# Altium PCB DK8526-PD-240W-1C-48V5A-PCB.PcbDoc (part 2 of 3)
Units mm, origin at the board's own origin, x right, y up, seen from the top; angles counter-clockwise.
Board outline 89.28 x 73.8 mm, 4 copper layers (Top Layer, Layer 1, Layer 2, Bottom Layer), stack 0.603 mm thick; 182 components, 162 nets, 518 pads, 506 vias.
Unrouted connection lines stored in the file: 4.
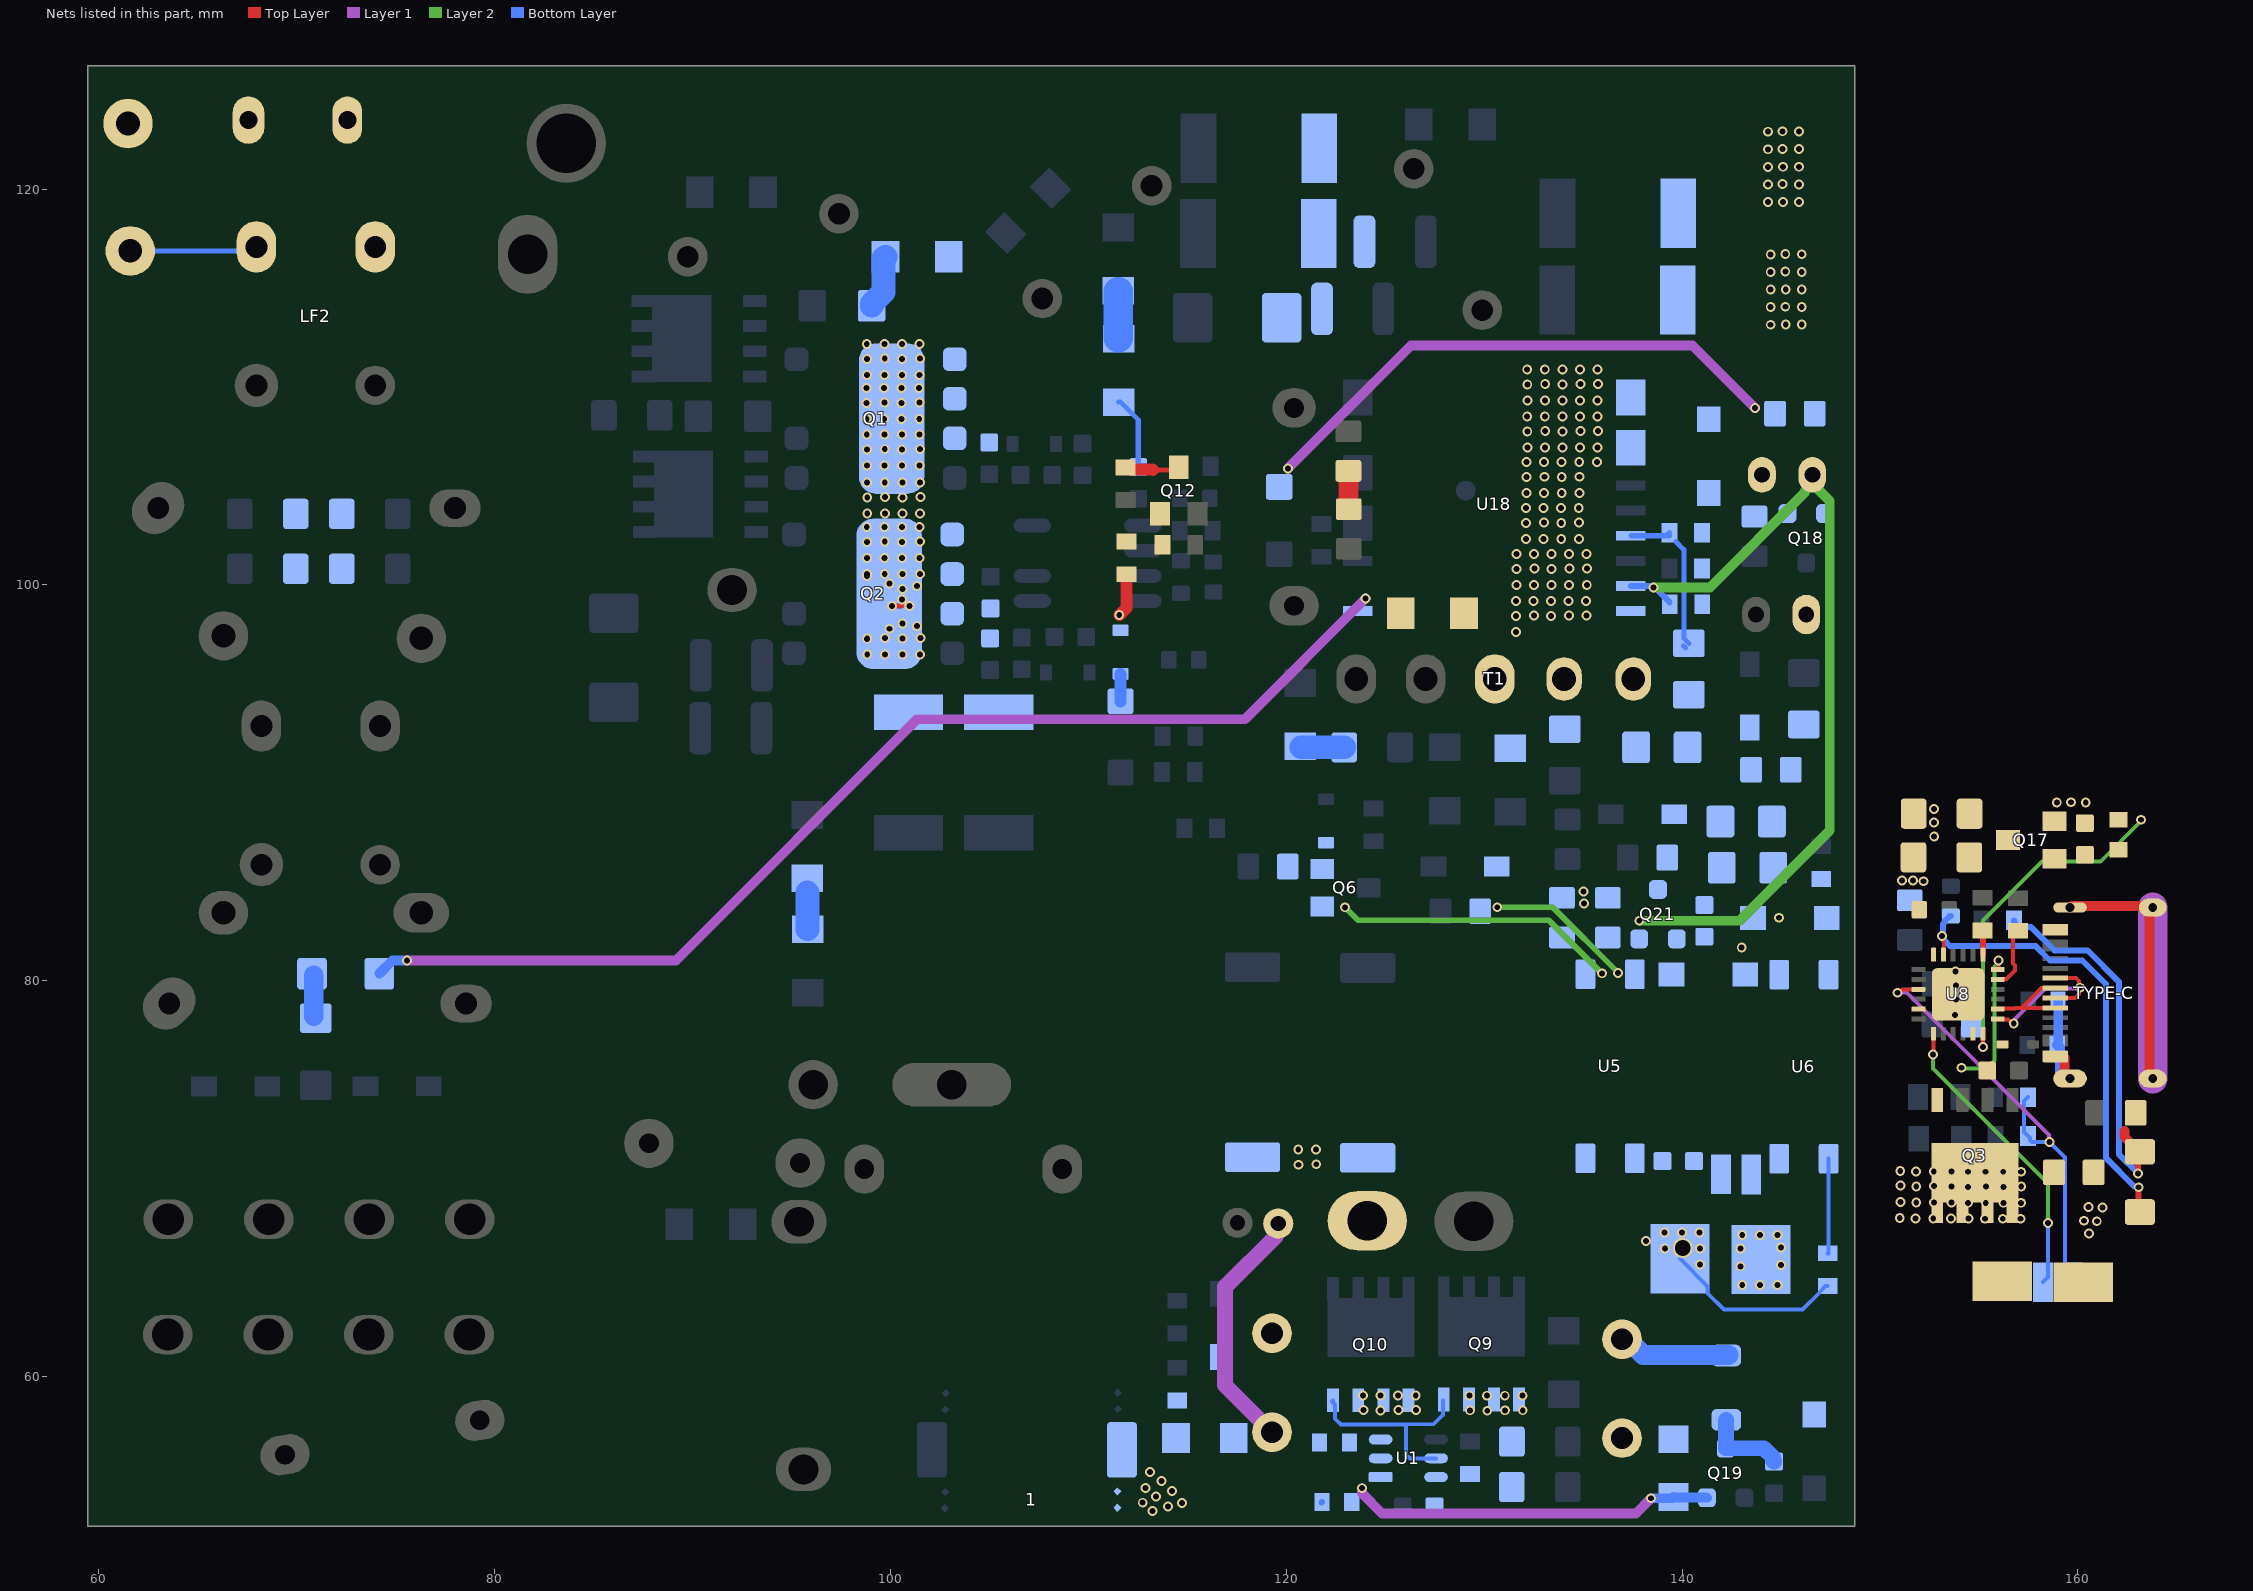
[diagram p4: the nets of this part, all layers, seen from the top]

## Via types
v1: diameter 0.5, hole 0.3, Top Layer to Bottom Layer, 439 vias
v2: diameter 0.5, hole 0.3, Top Layer to Bottom Layer, tented both sides, 64 vias
v3: diameter 0.5/0.5/0.5/0.5 (per signal layer), hole 0.3, Top Layer to Bottom Layer, tented both sides, 2 vias
v4: diameter 1, hole 0.8, Top Layer to Bottom Layer, 1 vias

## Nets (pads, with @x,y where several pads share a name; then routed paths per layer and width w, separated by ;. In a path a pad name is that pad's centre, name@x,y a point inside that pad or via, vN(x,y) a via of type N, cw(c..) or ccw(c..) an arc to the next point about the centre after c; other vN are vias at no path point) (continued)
NetD10_2: Q6.1 U5.3 ZD1.2 | length 14.4
  Layer 2 w0.3: v2(122.972,83.713) 123.627,83.058 133.271,83.058 v2(135.951,80.378)
NetD12_A: D12.A R36.2 | length 27.5
  Layer 1 w0.5: v2(120.079,105.88) 126.304,112.105 140.522,112.105 v2(143.682,108.944)
NetD14_2: D14.2 ZD3.2 | length 1.4
  Bottom Layer w0.6: D14.2@111.628,94.121 ZD3.2@111.628,95.512
NetD16_1: Q3.4 R63.1 U8.18 ZD4.1 | length 7.4
  Top Layer w0.2: U8.18@155.955,80.568 155.978,80.568 156.003,80.593 v2(156.003,81.016)
  Layer 2 w0.2: v2(154.129,75.604) 154.162,75.572 155.384,75.572 155.787,75.975 155.787,80.718 156.003,80.935 v2(156.003,81.016)
NetD18_1: TYPE-C.A6DP TYPE-C.B6DP U8.13 | length 8
  Top Layer w0.2: U8.13@155.955,78.068 155.98,78.043 156.483,78.043 156.683,77.843 v2(156.764,77.843) ; TYPE-C.A6DP@159.045,79.131 159.864,79.131 160.061,79.328 160.061,79.591 v2(160.119,79.648) ; TYPE-C.B6DP@159.045,80.131 159.92,80.131 160.061,79.989 160.061,79.787 160.138,79.71 v2@160.18,79.71
  Layer 1 w0.2: v2(156.764,77.843) 156.822,77.9 156.822,78.057 158.385,79.62 160.091,79.62 v2(160.119,79.648)
NetD19_1: TYPE-C.A7DM TYPE-C.B7DM U8.14 | length 5.4
  Top Layer w0.2: U8.14@155.955,78.568 155.982,78.596 156.828,78.596 156.863,78.631 ; 156.867,78.634 156.863,78.631 157.153,78.631 ; TYPE-C.B7DM@159.045,78.631 157.153,78.631 ; TYPE-C.A7DM@159.045,79.631 158.153,79.631 157.153,78.631
NetF1_1: F1.1 L.1 | length 0.4
  Top Layer w0.254: F1.1@67.282,123.22 F1.1@67.555,123.493
NetF1_2: 
NetFR1_2: 
NetFR2_2: 
NetFR3_1: FR3.1 U6.4 ZD2.2
NetL5_2: D13.2 L5.2 L6.2 R10.2 R12.2
NetL8_2: L8.2 U8.19 | length 1.2
  Top Layer w0.3: L8.2@155.186,82.546 155.205,82.527 U8.19@155.205,81.318
NetLF2_1: LF2.4@67.959,117.087 N.1 | length 6.5
  Bottom Layer w0.254: N.1@61.582,116.885 67.757,116.885 LF2.4@67.959,117.087
NetQ1_4: 
NetQ3_1: 
NetQ3_3: 
NetQ4_2: 
NetQ5_1: 
NetQ5_4: 
NetQ6_2: Q6.2 R23.2
NetQ7_4: 
NetQ8_1: 
NetQ9_4: Q9.4 Q10.4 U1.5GT | length 10.6
  Bottom Layer w0.2: Q10.4@122.372,58.796 122.318,58.742 122.473,58.588 122.473,57.867 122.758,57.582 126.053,57.582 ; U1.5GT@127.569,55.866 126.252,55.866 126.053,56.065 126.053,57.589 127.439,57.589 127.91,58.06 Q9.4@127.91,58.784
NetQ9_5: 
NetQ11_1: 
NetQ11_2: 
NetQ12_1: Q12.1 R49.2 R54.2
NetQ12_3: Q12.3 R42.2 | length 2.8
  Top Layer w0.254: 113.273,105.809 114.428,105.809 Q12.3@114.565,105.946
  Top Layer w0.6: R42.2@111.884,105.94 111.984,105.84 113.242,105.84 113.273,105.809
NetQ13_1: 
NetQ14_4: 
NetQ15_4: 
NetQ17_1: Q17.1 R65.1 R66.2 | length 0.2
  Top Layer w0.2: R65.1@161.943,86.512 R65.1@162.052,86.621
NetQ17_3: Q17.3 R61.1 R62.1 | length 0
  Top Layer w0.2: R62.1@154.517,88.458 R62.1@154.531,88.444 ; R61.1@154.521,86.236 R61.1@154.535,86.222
NetR2_2: R2.2 R4.1 | length 1.9
  Top Layer w0.254: R2.2@123.143,105.764 R2.2@123.151,105.756 ; R4.1@123.151,103.84 R4.1@123.16,103.831
  Top Layer w1: R4.1@123.151,103.84 R2.2@123.151,105.756
NetR3_2: R3.2 R5.1 | length 2.3
  Bottom Layer w1.5: R5.1@111.506,112.487 R3.2@111.506,114.817
NetR4_2: 
NetR5_2: R5.2 R9.1 | length 3.7
  Bottom Layer w0.254: R5.2@111.533,109.237 111.633,109.237 112.521,108.349 R9.1@112.521,105.956
NetR15_2: 
NetR16_2: U8.11
NetR21_1: 
NetR28_1: R28.1 U5.4 | length 7.5
  Layer 2 w0.3: v2(130.663,83.716) 133.462,83.716 136.763,80.415 v2(136.763,80.394)
NetR29_2: 
NetR32_2: 
NetR33_2: R33.2 R34.1 | length 2.3
  Bottom Layer w0.5: R34.1@70.766,80.357 R34.1@70.859,80.264 ; R33.2@70.859,78.206 R33.2@70.953,78.112
  Bottom Layer w1: R33.2@70.859,78.206 R34.1@70.859,80.264
NetR39_1: 
NetR39_2: R13.2 R40.1 T1.1
NetR41_1: R41.1 R45.2 | length 1.9
  Bottom Layer w1.2: 95.798,84.455 95.805,84.449 R41.1@95.805,82.606
NetR48_1: "U1.6K SRD" R48.1
NetR49_1: R49.1 ZD3.1 | length 2.3
  Top Layer w0.6: v2(111.56,98.475) 111.929,98.843 111.929,100.44 112.029,100.44 R49.1@112.063,100.475
NetR51_2: U8.5
NetR57_2: "U1.3 TW" R57.2
NetR60_2: "U1.1  HVCC" C30.1 Q19.1E R70.1 | length 18.5
  Layer 1 w0.5: v3(123.825,54.356) 123.825,54.102 124.841,53.086 137.668,53.086 v3(138.43,53.848)
  Bottom Layer w0.5: v3(138.43,53.848) 139.511,53.848 C30.1@139.573,53.91 139.592,53.891 141.238,53.891 Q19.1E@141.256,53.872
NetR65_1: R64.2 U8.17 | length 3.2
  Top Layer w0.2: U8.17@155.955,80.068 155.98,80.093 156.396,80.093 156.825,80.523 156.825,80.773 156.724,80.875 156.724,82.271 R64.2@156.976,82.523
NetR66_1: R65.2 U8.12 | length 17.2
  Top Layer w0.2: U8.12@155.205,77.318 155.207,77.317 155.207,76.658 v2(155.209,76.656)
  Layer 2 w0.2: v2(155.209,76.656) 155.209,83.039 158.202,86.033 161.161,86.033 163.195,88.066 v2(163.195,88.138)
NetR70_2: 
NetR71_1: pad.16@143.494,70.208 pad.16@159.766,64.77 R71.1 R72.1 U6.2 U8.3 | length 23.1
  Top Layer w0.2: v2(150.885,79.394) 150.967,79.394 151.141,79.568 U8.3@151.955,79.568
  Layer 1 w0.2: v2(150.885,79.394) 151.365,79.394 158.547,72.212 158.547,71.884 v2(158.572,71.859)
  Bottom Layer w0.2: R71.1@157.483,74.118 157.289,73.923 157.289,72.35 R72.1@157.488,72.15 157.589,72.049 157.589,71.949 157.679,71.859 v2(158.572,71.859) 159.354,71.077 159.354,65.787 159.366,65.775 159.366,65.17 pad.16@159.766,64.77
NetR73_1: R69.1 U6.1 | length 4.8
  Bottom Layer w0.2: R69.1@147.361,66.226 147.41,66.226 U6.1@147.41,71.009
NetR73_2: pad.16@141.976,70.211 pad.16@158.248,64.774 R77.1 U8.7 | length 15.1
  Top Layer w0.2: v2(152.68,76.276) 152.705,76.301 U8.7@152.705,77.318
  Layer 2 w0.2: v2(152.68,76.276) 152.68,75.57 158.494,69.756 v2(158.494,67.759)
  Bottom Layer w0.2: pad.16@158.248,64.774 158.494,65.02 v2(158.494,67.759)
NetRCS1_1: 
NetRS1_2: C9.1 Q1.1 Q1.2 Q1.3 Q1.9 Q2.1 Q2.2 Q2.3 Q2.9 R11.1 R11.2 R25.1 R26.1 R27.1 RS1.2 RS2.2 | length 3.6
  Top Layer w0.254: v1(100.076,98.933) 100.543,98.933 100.579,98.969 v1(100.579,99.272)
  Bottom Layer w1.2: C9.1@99.05,114.109 99.05,114.209 99.645,114.803 99.645,116.494 R11.2@99.744,116.594
  other v1: 98.826,96.486 99.715,96.486 100.604,96.486 101.493,96.486 98.806,97.282 98.825,97.292 100.603,97.292 99.73,97.316 101.508,97.316 99.949,97.79 101.346,97.917 100.599,98.054 100.965,98.933 100.603,99.8 101.346,99.949 99.949,100.076 98.806,100.457 98.806,100.457 98.821,100.562 99.71,100.562 100.599,100.562 101.488,100.562 98.807,101.366 99.696,101.366 100.585,101.366 101.474,101.366 98.806,102.172 99.711,102.196 100.584,102.172 101.489,102.196 98.802,102.934 99.691,102.934 100.58,102.934 101.469,102.934 98.826,103.621 99.715,103.621 100.604,103.621 101.493,103.621 98.825,104.428 100.603,104.428 99.73,104.451 101.508,104.451 98.821,105.189 99.71,105.189 100.599,105.189 101.488,105.189 98.807,106.032 99.696,106.032 100.585,106.032 101.474,106.032 98.806,106.839 100.584,106.839 99.711,106.862 101.489,106.862 98.802,107.6 99.691,107.6 100.58,107.6 101.469,107.6 98.787,108.385 99.676,108.385 100.565,108.385 101.454,108.385 98.786,109.191 100.564,109.191 99.691,109.215 101.469,109.215 98.782,109.953 99.671,109.953 100.56,109.953 101.449,109.953 98.807,110.621 99.696,110.621 100.585,110.621 101.474,110.621 98.806,111.427 100.584,111.427 99.711,111.451 101.489,111.451 98.802,112.189 99.691,112.189 100.58,112.189 101.469,112.189
NewNet: 
pfcsw: R77.2 U5.1
PGND: C22.1 C23.1 C24.1 C43.2 C49.2 C50.2 C51.2 EC4.2 EC6.2 R24.2 R46.1 RS4.1 RS5.2 T1.3 U6.3 U18.1GND U18.2GND U18.8GND ZD2.1 ZD5.1 ZD6.1
  other v1: 131.607,97.626 131.606,98.432 133.384,98.432 132.511,98.456 134.289,98.456 135.178,98.456 131.602,99.194 132.491,99.194 133.38,99.194 134.269,99.194 135.158,99.194 131.632,100.002 132.521,100.002 133.41,100.002 134.299,100.002 135.188,100.002 131.631,100.808 133.409,100.808 132.536,100.832 134.314,100.832 135.203,100.832 131.627,101.57 132.516,101.57 133.405,101.57 134.294,101.57 135.183,101.57 132.12,102.328 133.009,102.328 133.898,102.328 134.787,102.328 132.119,103.135 133.897,103.135 133.024,103.158 134.802,103.158 132.115,103.896 133.004,103.896 133.893,103.896 134.782,103.896 132.145,104.642 133.034,104.642 133.923,104.642 134.812,104.642 132.144,105.448 133.049,105.472 133.922,105.448 134.827,105.472 132.14,106.21 133.029,106.21 133.918,106.21 134.807,106.21 135.696,106.21 132.182,106.956 133.071,106.956 133.96,106.956 134.849,106.956 135.738,106.956 132.181,107.762 133.959,107.762 133.086,107.786 134.864,107.786 135.753,107.786 132.177,108.524 133.066,108.524 133.955,108.524 134.844,108.524 135.733,108.524 132.182,109.319 133.071,109.319 133.96,109.319 134.849,109.319 135.738,109.319 132.181,110.125 133.959,110.125 133.086,110.149 134.864,110.149 135.753,110.149 132.177,110.887 133.066,110.887 133.955,110.887 134.844,110.887 135.733,110.887 144.482,113.152 145.244,113.156 146.05,113.157 144.482,114.041 146.05,114.046 145.22,114.061 144.482,114.93 145.244,114.934 146.05,114.935 144.482,115.819 146.05,115.824 145.22,115.839 144.482,116.708 146.05,116.713 145.22,116.728 144.34,119.352 145.102,119.356 145.908,119.357 144.34,120.241 145.908,120.246 145.078,120.261 144.34,121.13 145.102,121.134 145.908,121.135 144.34,122.019 145.908,122.024 145.078,122.039 144.34,122.908 145.908,122.913 145.078,122.928
  other v2: 143.017,81.676 144.907,83.185 135.042,83.906 135.031,84.52
Q11-2: 
q18b: Q18.3B R76.1 ZD5.2
Q21-B: Q21.3B R81.2 ZD6.2
Q21-C: C48.1 C49.1 C50.1 D24.K Q21.2C R81.1
R8-1: C8.2 R8.1 | length 2.3
  Bottom Layer w0.254: C8.2@120.701,91.849 C8.2@120.755,91.794
  Bottom Layer w1.2: C8.2@120.755,91.794 R8.1@122.93,91.794
r13: D22.A R13.1 R75.1
R14-7: 
R72: 
r75: C42.2 R75.2
RX1: RX1.1 RX2.1 RX3.2 RX4.2
SGND: 1.2@111.47,53.369 1.2@111.47,54.194 C26.2 C28.2 C30.2 C33.1 C35.1 C36.1 C37.2 C40.2 CY2.2 CY3.1 EC1.2 EC5.2 pad.15 pad.16@143.989,65.918 pad.16@160.274,64.77 Q9.1 Q9.2 Q9.3 Q10.1 Q10.2 Q10.3 Q17.2 R37.1 R38.1 R57.1 R66.1 RS6.1 U1.2GND U5.2 U8.23 U8.24 U8.25 ZD7.1 | length 36.5
  Top Layer w0.2: v2(153.145,82.255) 153.145,82.174 153.228,82.091 153.228,81.341 U8.23@153.205,81.318
  Top Layer w0.3: v2(163.079,69.566) 163.079,68.373 RS6.1@163.139,68.313
  Layer 1 w0.8: EC5.2@119.282,57.187 116.9,59.568 116.9,64.504 119.456,67.06 119.456,67.591 pad.15@119.595,67.73
  Bottom Layer w0.3: C35.1@153.588,83.268 153.523,83.268 153.288,83.033 153.288,82.968 153.183,82.864 153.183,82.293 v2(153.145,82.255) 153.145,82.201 153.245,82.101 153.245,82.046 153.542,81.748 157.877,81.748 158.6,81.026 160.227,81.026 161.417,79.836 161.417,71.05 162.863,69.604 163.041,69.604 v2(163.079,69.566)
  other v1: 113.239,53.195 114.018,53.431 112.746,53.623 114.742,53.618 113.416,53.932 114.234,54.212 112.89,54.365 113.698,54.72 113.12,55.167 130.159,58.269 124.769,58.287 129.286,58.293 131.064,58.293 131.953,58.293 123.896,58.31 125.674,58.31 126.563,58.31 129.266,59.031 130.155,59.031 131.044,59.031 131.933,59.031 123.876,59.048 124.765,59.048 125.654,59.048 126.543,59.048 143.045,64.622 143.934,64.622 144.823,64.622 142.963,65.571 145.011,65.636 142.963,66.46 145.011,66.525 143.045,67.149 143.934,67.149 144.823,67.149 120.61,70.703 121.515,70.727 120.606,71.465 121.495,71.465 160.403,89.013 158.94,89.018 159.655,89.022
  other v2: 160.566,67.23 160.961,67.848 160.316,67.872 161.241,68.548 160.549,68.573 153.792,78.264 153.844,79.044 153.843,79.752 153.827,80.46
SGND1: 
SGND2: C32.1 C34.1 C41.1 R68.2 RS6.2 TYPE-C.A1B12 TYPE-C.B1A12 TYPE-C.H | length 47.1
  Top Layer w0.3: v2(163.05,70.265) 163.05,71.21 RS6.2@163.065,71.224
  Top Layer w0.5: TYPE-C.A1B12@159.045,76.18 159.277,76.18 159.327,76.13 159.327,75.292 159.558,75.061 TYPE-C.H@159.609,75.06 TYPE-C.H@159.694,75.146 ; TYPE-C.H@159.609,83.7 159.695,83.786 TYPE-C.H@163.618,83.786 ; 162.354,72.4 162.354,72.112 163.104,71.361 RS6.2@163.139,71.361 ; TYPE-C.H@163.789,75.06 163.618,75.232 163.618,83.529 TYPE-C.H@163.789,83.7
  Layer 1 w1.5: TYPE-C.H@163.789,75.061 TYPE-C.H@163.789,83.7
  Bottom Layer w0.3: R68.2@156.781,83.058 156.781,82.958 157.031,82.708 157.646,82.708 158.828,81.526 160.501,81.526 162.076,79.95 162.076,71.239 v2(163.05,70.265)
  Bottom Layer w0.5: C41.1@159.015,78.991 159.015,76.814 C34.1@158.959,76.758 159.094,76.623 159.094,75.292 TYPE-C.H@159.176,75.292 ; TYPE-C.H@159.176,75.292 159.378,75.292 TYPE-C.H@159.609,75.06 159.407,75.061 TYPE-C.H@159.176,75.292
T-1: 
VC: Q19.2C R82.1 R83.2 | length 4.2
  Bottom Layer w0.8: Q19.2C@142.206,56.372 144.134,56.372 144.603,55.904 144.603,55.752 R82.1@144.653,55.702 ; R83.2@142.24,57.811 142.223,57.794 142.223,56.447 Q19.2C@142.256,56.447
vcc1: R79.1 T1.2
VCC_EXT: C24.2 C43.1 C51.1 D7.A EC6.1 Q18.1E Q21.1E R36.1 U18.7VCC | length 42.4
  Layer 2 w0.5: v2(137.841,83.032) 142.912,83.032 147.469,87.588 147.469,104.245 146.656,105.058 146.521,105.058 146.217,104.755 146.217,104.688 141.408,99.879 v2(138.564,99.879) ; EC6.1@146.587,105.058 EC6.1@146.587,105.569
  Bottom Layer w0.3: U18.7VCC@137.414,99.949 138.552,99.949 C24.2@139.377,99.124
VCCF: C26.1 C44.2 D23.K R70.2 | length 0
  Bottom Layer w0.3: R70.2@121.79,53.636 R70.2@121.806,53.652
VOUT: C33.2 CY1.2 EC1.1 EC5.1 pad.13@124.097,67.87 pad.16@139.897,65.958 pad.16@156.182,64.81 Q3.5 Q3.6 Q3.7 Q3.8 Q3.9 R61.2 R62.2 R67.2 R69.2 R83.1 | length 15
  Bottom Layer w0.2: pad.16@139.897,65.958 141.297,64.558 141.297,64.208 142.127,63.378 146.09,63.378 146.961,64.249 146.961,64.276 147.261,64.576 R69.2@147.361,64.576
  Bottom Layer w1: EC1.1@136.969,61.887 137.239,61.887 138.04,61.087 R83.1@142.343,61.087
  other v1: 140.909,65.667 139.13,66.473 140.908,66.473 138.181,66.855 139.11,67.273 139.999,67.273 140.888,67.273 155.32,67.972 156.209,67.972 157.098,67.972 151.808,67.988 152.697,67.988 153.586,67.988 154.475,67.988 151.004,68.015 154.461,68.78 155.35,68.78 156.239,68.78 157.128,68.78 151.838,68.796 152.727,68.796 153.616,68.796 151.034,68.824 151.837,69.603 153.615,69.603 154.46,69.586 156.238,69.586 152.742,69.626 155.365,69.61 157.143,69.61 151.049,69.654 151.833,70.364 152.722,70.364 153.611,70.364 154.456,70.348 155.345,70.348 156.234,70.348 157.123,70.348 151.029,70.392
  other v2: 152.209,85.027 151.121,85.075 151.674,85.058 152.745,87.296 152.735,87.994 152.74,88.676
  other v4: 140.035,66.497
VOUT1: 
VS: R40.2 R46.2 U18.5VS | length 7.6
  Bottom Layer w0.254: U18.5VS@137.414,102.489 139.205,102.489 139.269,102.553 R46.2@139.361,102.645 ; R46.2@139.357,102.465 R46.2@139.357,102.489 ; R46.2@139.692,102.191 140.095,101.788 140.095,99.668 140.104,99.659 140.104,98.388 140.095,98.38 140.095,97.303 R40.2@140.344,97.054 ; R40.2@140.084,96.918 R40.2@140.184,96.818
XCD: C23.2 R34.2 U18.9XCD | length 57.7
  Layer 1 w0.5: v2(75.565,81.026) 89.154,81.026 101.346,93.218 117.912,93.218 v2(124.012,99.318)
  Bottom Layer w0.5: R34.2@74.166,80.357 74.835,81.026 v2(75.565,81.026)
Y3: F1.2 LF2.1@73.959,117.087
pads on no net: 1.1@102.771,58.333 1.1@102.796,59.158 1.2@111.496,58.358 1.2@111.496,59.183 NTC1.2@87.212,72.456 NTC1.3 T2.1 TYPE-C.A8 TYPE-C.B8 U4.7NC U8.8 U8.9 U8.10 U8.20 U8.21 U18.3NC U18.15GND
copper on no net: | length 1.9
  Bottom Layer w1.2: 88.346,108.473 90.276,108.473

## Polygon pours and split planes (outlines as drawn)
GND on Bottom Layer "NONET_L-01_P-001" (hatched Horizontal grid 0.2 track 0.2, pour order 526): 117.998,81.407 126.35,81.407 126.482,81.275 126.482,80.132 126.299,79.949 118.014,79.949 117.894,80.069 117.894,81.303
VOUT on Bottom Layer "NONET_L-01_P-001" (hatched Horizontal grid 0.2 track 0.2, pour order 653): 122.917,71.833 122.717,71.632 122.717,69.255 122.066,68.604 122.066,67.195 122.825,66.436 125.286,66.436 126.079,67.228 126.079,71.536 125.782,71.833
SGND on Bottom Layer "NONET_L-01_P-001" (hatched Horizontal grid 0.2 track 0.2, pour order 652): 121.798,71.947 121.736,72.009 116.809,72.009 116.626,71.827 116.626,70.585 116.904,70.308 121.641,70.308 122.011,70.678 122.011,71.722 121.798,71.935
HV on Bottom Layer "NONET_L-01_P-001" (hatched Horizontal grid 0.2 track 0.2, pour order 355): 117.354,112.43 118.468,111.315 121.222,111.315 121.687,110.85 121.687,107.951 121.457,107.722 117.654,107.722 113.905,111.471 113.905,112.778
NetC8_2 on Bottom Layer "NONET_L-01_P-001" (hatched Horizontal grid 0.2 track 0.2, pour order 651): 127.29,118.798 125.419,118.798 125.031,118.411 125.031,116.104 122.843,113.916 122.843,112.566 122.268,111.99 122.268,108.894 122.603,108.559 124.238,108.559 124.427,108.748 124.427,111.707 127.504,114.784 127.504,118.584
NetL5_2 on Bottom Layer "NONET_L-01_P-001" (hatched Horizontal grid 0.2 track 0.2, pour order 650): 118.745,123.825 118.528,123.608 118.528,112.406 118.985,111.949 121.451,111.949 122.259,112.758 122.259,114.073 124.077,115.891 124.436,116.249 124.436,119.388 122.719,121.105 122.719,123.534 122.428,123.825
GND on Bottom Layer "NONET_L-01_P-001" (hatched Horizontal grid 0.2 track 0.2, pour order 443): 128.982,125.377 129.372,125.766 135.092,125.766 135.587,125.271 135.587,112.317 135.622,112.282 135.408,112.067 131.961,112.067 131.186,112.842 129.452,112.842 128.982,113.312
SGND on Bottom Layer "NONET_L-01_P-001" (hatched Horizontal grid 0.2 track 0.2, remove dead copper, pour order 514): 21 vertices, not listed, extent 134.508,52.778 148.419,71.797
NetQ9_4 on Bottom Layer "NONET_L-01_P-001" (hatched Horizontal grid 0.2 track 0.2, pour order 644): 30 vertices, not listed, extent 122.006,55.732 128.221,59.437
NetR57_2 on Bottom Layer "NONET_L-01_P-001" (hatched Horizontal grid 0.2 track 0.2, pour order 484): 125.261,57.013 122.837,57.013 122.742,56.918 122.742,56.389 122.833,56.298 123.511,56.298 123.842,56.629 125.275,56.629 125.365,56.719 125.365,56.91
GND on Bottom Layer "NONET_L-01_P-001" (hatched Horizontal grid 0.2 track 0.2, pour order 369): 24 vertices, not listed, extent 111.79,97.623 117.441,106.628
GND on Bottom Layer "NONET_L-01_P-001" (hatched Horizontal grid 0.2 track 0.2, pour order 643): 19 vertices, not listed, extent 108.077,67.945 121.139,88.218
GND on Bottom Layer "NONET_L-01_P-001" (hatched Horizontal grid 0.2 track 0.2, pour order 642): 98.931,89.358 109.778,89.358 110.387,88.749 113.55,88.749 113.924,88.375 113.924,83.698 107.95,77.724 104.267,77.724 102.108,79.883
GND on Bottom Layer "NONET_L-01_P-001" (hatched Horizontal grid 0.2 track 0.2, pour order 637): 21 vertices, not listed, extent 60.052,52.791 99.476,69.037
NetBD1_1 on Bottom Layer "NONET_L-01_P-001" (hatched Horizontal grid 0.2 track 0.2, pour order 633): 89.677,68.908 77.85,68.908 77.526,68.584 77.526,57.729 78.494,56.761 80.339,56.761 90.025,66.448 90.025,68.56
NetBD1_3 on Bottom Layer "NONET_L-01_P-001" (hatched Horizontal grid 0.2 track 0.2, pour order 631): 20 vertices, not listed, extent 60.715,61.044 70.21,87.168
NetBD1_2 on Bottom Layer "NONET_L-01_P-001" (hatched Horizontal grid 0.2 track 0.2, pour order 628): 24 vertices, not listed, extent 72.465,61.099 80.518,87.183
RX1 on Bottom Layer "NONET_L-01_P-001" (solid, pour order 6): 73.193,104.385 73.193,99.809 73.022,99.638 69.207,99.638 69.076,99.768 69.076,104.275 69.298,104.497 73.081,104.497
NetCX1_2 on Bottom Layer "NONET_L-01_P-001" (hatched Horizontal grid 0.2 track 0.2, pour order 614): 68.952,112.382 68.939,112.395 62.869,112.395 62.013,111.538 62.013,89.002 62.718,88.297 68.451,88.297 69.406,89.253 69.406,92.317 67.792,93.931 67.792,105.463 69.282,106.954 69.282,112.086 68.972,112.397
NetLF2_1 on Bottom Layer "NONET_L-01_P-001" (hatched Horizontal grid 0.2 track 0.2, pour order 613): 60.658,118.236 60.143,117.721 60.143,116.071 60.623,115.592 65.637,115.592 67.384,113.845 67.908,113.321 68.821,113.321 69.3,113.8 69.3,117.455 68.519,118.236
NetF1_1 on Bottom Layer "NONET_L-01_P-001" (hatched Horizontal grid 0.2 track 0.2, pour order 611): 60.071,122.301 60.071,125.073 60.571,125.572 67.926,125.572 68.444,125.054 68.444,122.462 68.029,122.047 60.338,122.047 60.074,122.311
NetCX1_1 on Bottom Layer "NONET_L-01_P-001" (hatched Horizontal grid 0.2 track 0.2, pour order 608): 75.052,112.348 72.453,112.348 71.798,111.693 71.798,108.283 74.676,105.404 74.676,95.467 72.868,93.659 72.868,88.714 73.283,88.299 79.051,88.299 79.629,88.877 79.629,107.787 75.253,112.163 75.073,112.342
NetCX1_2 on Bottom Layer "NONET_L-01_P-001" (hatched Horizontal grid 0.2 track 0.2, pour order 607): 68.952,112.382 68.939,112.395 62.869,112.395 60.716,110.241 60.716,88.726 61.145,88.297 68.451,88.297 69.406,89.253 69.406,94.09 67.792,95.704 67.792,105.463 69.282,106.954 69.282,112.086 68.972,112.397
NetLF2_1 on Bottom Layer "NONET_L-01_P-001" (hatched Horizontal grid 0.2 track 0.2, pour order 606): 60.753,118.331 60.143,117.721 60.143,116.071 60.623,115.592 65.637,115.592 67.384,113.845 67.908,113.321 68.821,113.321 69.3,113.8 69.3,117.455 68.424,118.331
Y3 on Bottom Layer "NONET_L-01_P-001" (hatched Horizontal grid 0.2 track 0.2, pour order 605): 71.999,124.758 71.894,124.653 71.894,113.653 72.353,113.194 74.586,113.194 75.025,113.633 75.025,124.735 74.792,124.968 72.205,124.968 71.985,124.748
Y3 on Bottom Layer "NONET_L-01_P-001" (hatched Horizontal grid 0.2 track 0.2, pour order 598): 71.999,124.758 71.894,124.653 71.894,113.653 72.353,113.194 74.586,113.194 75.025,113.633 75.025,124.735 74.792,124.968 72.205,124.968 71.985,124.748
NetF1_1 on Bottom Layer "NONET_L-01_P-001" (hatched Horizontal grid 0.2 track 0.2, pour order 597): 60.071,122.301 60.071,125.073 60.571,125.572 67.926,125.572 68.444,125.054 68.444,122.462 67.872,121.89 60.495,121.89 60.074,122.311
SGND on Bottom Layer "NONET_L-01_P-001" (hatched Horizontal grid 0.2 track 0.2, remove dead copper, pour order 586): 19 vertices, not listed, extent 153.091,66.438 164.555,89.449
SGND on Bottom Layer "NONET_L-01_P-001" (hatched Horizontal grid 0.2 track 0.2, pour order 578): 155.341,80.889 153.738,80.889 153.614,80.765 153.614,77.507 153.918,77.203 155.695,77.203 156.161,77.669 156.161,80.069
SGND2 on Bottom Layer "NONET_L-01_P-001" (hatched Horizontal grid 0.2 track 0.2, pour order 577): 158.41,83.107 158.388,83.129 158.388,84.415 158.927,84.954 164.313,84.954 164.797,84.47 164.797,72.259 164.57,72.033 162.957,72.033 162.663,72.327 162.663,80.415 161.036,82.042 159.131,82.042 158.406,82.767 158.406,83.107
SGND on Bottom Layer "NONET_L-01_P-001" (hatched Horizontal grid 0.2 track 0.2, pour order 576): 159.893,71.501 164.098,71.501 164.517,71.082 164.517,67.719 164.269,67.471 161.988,67.471 161.662,67.145 161.065,66.548 160.147,66.548 159.81,66.885 159.81,71.434 159.863,71.486
VOUT on Bottom Layer "NONET_L-01_P-001" (hatched Horizontal grid 0.2 track 0.2, pour order 574): 158.461,70.739 150.884,70.739 150.67,70.525 150.67,67.766 150.999,67.438 157.533,67.438 157.907,67.812 157.907,68.463 158.794,69.35 158.794,70.406
NetR71_1 on Bottom Layer "NONET_L-01_P-001" (hatched Horizontal grid 0.2 track 0.2, pour order 573): 157.826,74.688 157.82,74.694 157.113,74.694 156.941,74.522 156.941,71.67 157.046,71.565 158.854,71.565 158.854,73.666 157.831,74.688
NetC39_1 on Bottom Layer "NONET_L-01_P-001" (hatched Horizontal grid 0.2 track 0.2, pour order 572): 155.897,72.76 153.716,72.76 153.554,72.598 153.554,71.496 153.67,71.38 153.676,71.385 155.99,71.385 156.24,71.635 156.24,72.65 156.128,72.762 155.901,72.762
NetC38_1 on Bottom Layer "NONET_L-01_P-001" (hatched Horizontal grid 0.2 track 0.2, pour order 571): 156.095,74.804 156.08,74.819 153.736,74.819 153.598,74.681 153.598,73.525 153.675,73.448 156.041,73.448 156.239,73.646 156.239,74.654 156.086,74.806
NetC39_2 on Bottom Layer "NONET_L-01_P-001" (hatched Horizontal grid 0.2 track 0.2, pour order 570): 150.738,73.115 150.618,72.995 150.618,71.656 150.839,71.435 152.404,71.435 152.51,71.541 152.51,72.889 152.284,73.115
NetC38_2 on Bottom Layer "NONET_L-01_P-001" (hatched Horizontal grid 0.2 track 0.2, pour order 569): 152.4,75.057 150.95,75.057 150.637,74.743 150.637,73.679 150.806,73.51 152.395,73.51 152.565,73.68 152.565,74.891 152.404,75.052
NetC40_1 on Bottom Layer "NONET_L-01_P-001" (hatched Horizontal grid 0.2 track 0.2, pour order 568): 153.113,78.454 151.447,78.454 150.768,77.775 150.768,77.056 150.825,76.999 153.022,76.999 153.225,77.202 153.225,78.338 153.1,78.463
NetC37_1 on Bottom Layer "NONET_L-01_P-001" (hatched Horizontal grid 0.2 track 0.2, pour order 566): 18 vertices, not listed, extent 150.703,79.26 153.12,82.912
VOUT on Bottom Layer "NONET_L-01_P-001" (hatched Horizontal grid 0.2 track 0.2, pour order 560): 152.957,89.368 152.949,89.36 150.979,89.36 150.72,89.101 150.72,83.559 150.719,83.559 150.796,83.482 152.327,83.482 152.518,83.673 152.518,85.765 153.416,86.663 153.416,88.9 153.162,89.154
VOUT on Bottom Layer "NONET_L-01_P-001" (hatched Horizontal grid 0.2 track 0.2, pour order 540): 137.232,63.071 137.219,63.083 136.357,63.083 135.975,62.701 135.975,61.45 135.987,61.45 136.535,60.902 137.62,60.902 138.076,61.358 138.076,62.233 137.244,63.065
VOUT on Bottom Layer "NONET_L-01_P-001" (hatched Horizontal grid 0.2 track 0.2, pour order 539): 119.585,63.523 118.332,63.523 117.909,63.101 117.909,61.534 118.347,61.097 119.862,61.097 120.256,61.49 120.256,62.853 119.593,63.516
SGND on Bottom Layer "NONET_L-01_P-001" (hatched Horizontal grid 0.2 track 0.2, pour order 538): 19 vertices, not listed, extent 118.714,59.697 121.822,68.519
NetR73_1 on Bottom Layer "NONET_L-01_P-001" (hatched Horizontal grid 0.2 track 0.2, pour order 537): 148.034,71.764 148.021,71.777 147.005,71.777 146.85,71.621 146.85,65.883 146.947,65.786 147.9,65.786 148.175,66.061 148.175,71.634 148.029,71.779
VOUT on Bottom Layer "NONET_L-01_P-001" (hatched Horizontal grid 0.2 track 0.2, pour order 536): 19 vertices, not listed, extent 137.528,63.381 148.375,67.615
NetBD1_1 on Bottom Layer "NONET_L-01_P-001" (hatched Horizontal grid 0.2 track 0.2, pour order 534): 94.736,57.571 102.83,57.571 102.83,53.763 102.788,53.721 94.742,53.721 94.107,54.356 94.107,56.942
SGND on Bottom Layer "NONET_L-01_P-001" (hatched Horizontal grid 0.2 track 0.2, pour order 533): 112.868,57.566 111.499,57.566 111.186,57.253 111.186,53.639 111.945,52.88 116.323,52.88 116.476,53.033 116.476,53.54 114.501,55.515 113.688,55.515 112.972,56.231 112.972,57.462
VCCF on Bottom Layer "NONET_L-01_P-001" (hatched Horizontal grid 0.2 track 0.2, pour order 531): 113.538,58.166 113.538,56.388 113.919,56.007 114.911,56.007 115.025,55.893 115.039,55.908 115.039,58.243
GND on Bottom Layer "NONET_L-01_P-001" (hatched Horizontal grid 0.2 track 0.2, pour order 528): 115.751,82.071 115.341,81.661 115.341,80.165 115.741,79.765 119.706,79.765 119.976,80.035 119.976,81.569 119.474,82.071
NetQ6_2 on Bottom Layer "NONET_L-01_P-001" (hatched Horizontal grid 0.2 track 0.2, pour order 525): 122.174,86.106 120.904,86.106 120.62,86.39 119.714,86.39 119.634,86.31 119.634,85.221 119.704,85.151 122.314,85.151 122.381,85.219 122.381,86.043 122.323,86.102
NetD10_2 on Bottom Layer "NONET_L-01_P-001" (hatched Horizontal grid 0.2 track 0.2, pour order 524): 17 vertices, not listed, extent 121.162,83.253 123.164,87.376
NetC9_2 on Bottom Layer "NONET_L-01_P-001" (hatched Horizontal grid 0.2 track 0.2, pour order 349): 92.868,100.807 91.352,100.807 89.154,98.608 89.154,91.593 89.434,91.313 92.226,91.313 92.357,91.444 92.357,97.233 93.38,98.256 93.38,100.295
HV on Bottom Layer "NONET_L-01_P-001" (hatched Horizontal grid 0.2 track 0.2, pour order 350): 23 vertices, not listed, extent 83.9,97.468 91.136,121.04
NetC1_2 on Bottom Layer "NONET_L-01_P-001" (hatched Horizontal grid 0.2 track 0.2, pour order 351): 96.413,115.042 92.708,115.042 92.503,114.837 92.503,101.961 93.971,100.493 93.971,98.023 92.963,97.015 92.963,91.647 93.159,91.451 96.254,91.451 96.743,91.94 96.743,114.712
NetRS1_2 on Bottom Layer "NONET_L-01_P-001" (hatched Horizontal grid 0.2 track 0.2, pour order 352): 38 vertices, not listed, extent 98.338,90.993 107.385,115.043
HV on Bottom Layer "NONET_L-01_P-001" (hatched Horizontal grid 0.2 track 0.2, pour order 353): 28 vertices, not listed, extent 83.9,110.617 127.381,125.857
GAT2 on Bottom Layer "NONET_L-01_P-001" (hatched Horizontal grid 0.2 track 0.2, pour order 357): 106.927,107.537 105.998,107.537 105.91,107.449 105.91,106.778 105.312,106.179 103.043,106.179 102.677,105.813 102.677,105.111 102.905,104.883 106.661,104.883 107.017,105.239 107.017,107.447
CS2 on Bottom Layer "NONET_L-01_P-001" (hatched Horizontal grid 0.2 track 0.2, pour order 358): 108.284,101.092 104.533,101.092 104.358,100.917 104.358,100.081 104.527,99.912 108.079,99.912 108.416,100.249 108.416,100.96
NetRS1_2 on Bottom Layer "NONET_L-01_P-001" (hatched Horizontal grid 0.2 track 0.2, pour order 359): 102.199,97.908 103.894,97.908 104.267,97.535 104.267,97.027 104.452,96.841 105.348,96.841 105.618,97.111 105.618,99.212 105.516,99.314 102.997,99.314
GAT1 on Bottom Layer "NONET_L-01_P-001" (hatched Horizontal grid 0.2 track 0.2, pour order 361): 102.341,97.111 102.341,95.969 103.207,95.104 107.994,95.104 108.178,95.288 108.178,95.939 107.883,96.233 104.288,96.233 103.784,96.738 103.784,97.185 103.593,97.375 102.605,97.375
GAT on Bottom Layer "NONET_L-01_P-001" (hatched Horizontal grid 0.2 track 0.2, pour order 362): 19 vertices, not listed, extent 106.088,96.901 110.302,105.967
NetC29_1 on Bottom Layer "NONET_L-01_P-001" (hatched Horizontal grid 0.2 track 0.2, pour order 363): 97.028,89.006 97.028,88.013 96.573,87.558 94.859,87.558 94.731,87.686 94.731,89.169 95.025,89.463 97.498,89.463
NetC29_1 on Bottom Layer "NONET_L-01_P-001" (hatched Horizontal grid 0.2 track 0.2, pour order 365): 107.361,90.17 110.363,90.17 110.871,89.662 113.748,89.662 114.113,90.027 114.113,92.978 114.023,93.068 113.347,93.068 112.697,92.419 109.61,92.419
FB on Bottom Layer "NONET_L-01_P-001" (hatched Horizontal grid 0.2 track 0.2, pour order 366): 17 vertices, not listed, extent 111.082,102.734 114.907,106.553
NetR5_2 on Bottom Layer "NONET_L-01_P-001" (hatched Horizontal grid 0.2 track 0.2, pour order 367): 112.218,109.982 112.956,109.243 112.956,105.613 112.839,105.496 112.183,105.496 112.038,105.641 112.038,108.215 111.728,108.526 110.824,108.526 110.665,108.684 110.665,109.796 110.672,109.796 110.858,109.982
NetC18_1 on Bottom Layer "NONET_L-01_P-001" (hatched Horizontal grid 0.2 track 0.2, pour order 368): 114.917,103.265 114.35,103.265 114.245,103.16 114.245,102.509 113.887,102.151 111.98,102.151 111.862,102.033 111.862,101.481 111.974,101.37 113.775,101.37 114.18,100.965 114.931,100.965 114.995,101.029 114.995,103.187
NetC12_2 on Bottom Layer "NONET_L-01_P-001" (hatched Horizontal grid 0.2 track 0.2, pour order 370): 113.458,99.523 111.861,99.523 111.802,99.464 111.802,99.061 113.77,97.093 114.34,97.093 114.554,97.307 114.554,98.181 113.691,99.044 113.691,99.29 113.454,99.527
NetR49_1 on Bottom Layer "NONET_L-01_P-001" (hatched Horizontal grid 0.2 track 0.2, pour order 373): 111.589,98.593 111.213,98.593 110.998,98.378 110.998,97.493 111.084,97.407 111.201,97.29 111.95,97.29 112.069,97.409 112.069,98.113
NetRS1_2 on Bottom Layer "NONET_L-01_P-001" (hatched Horizontal grid 0.2 track 0.2, pour order 376): 103.735,117.348 101.745,117.348 101.466,117.069 101.466,113.902 100.428,112.864 98.668,112.864 98.35,112.546 98.35,110.546 105.212,110.546 105.453,110.787 105.453,115.629
GND on Bottom Layer "NONET_L-01_P-001" (hatched Horizontal grid 0.2 track 0.2, pour order 377): 93.015,116.84 92.93,116.925 92.93,120.661 93.142,120.873 103.555,120.873 109.044,115.384 109.044,108.917 108.779,108.653 106.367,108.653 106.099,108.921 106.099,116.066 104.104,118.061 98.842,118.061 97.621,116.84
NetC2_1 on Bottom Layer "NONET_L-01_P-001" (hatched Horizontal grid 0.2 track 0.2, pour order 378): 121.121,99.556 119.581,99.556 119.066,99.041 119.066,95.095 120.057,94.104 123.984,94.104 124.452,94.571 124.452,96.284 123.842,96.894 122.237,96.894 121.469,97.663 121.469,99.209
XCD on Bottom Layer "NONET_L-01_P-001" (hatched Horizontal grid 0.2 track 0.2, pour order 379): 124.276,99.602 124.272,99.605 123.108,99.605 122.927,99.425 122.927,98.498 123.057,98.368 124.279,98.368 124.402,98.491 124.402,99.483 124.276,99.609
NetC14_2 on Bottom Layer "NONET_L-01_P-001" (hatched Horizontal grid 0.2 track 0.2, pour order 382): 28 vertices, not listed, extent 121.244,90.967 130.364,111.125
NetC17_1 on Bottom Layer "NONET_L-01_P-001" (hatched Horizontal grid 0.2 track 0.2, pour order 383): 119.07,102.215 120.353,102.215 120.681,101.887 122.259,101.887 122.552,101.594 124.268,101.594 124.414,101.448 124.414,101.068 124.337,100.991 119.061,100.991 118.944,101.107 118.944,102.089
PGND on Bottom Layer "NONET_L-01_P-001" (hatched Horizontal grid 0.2 track 0.2, pour order 386): 27 vertices, not listed, extent 129.579,90.993 142.477,125.817
NetD12_A on Bottom Layer "NONET_L-01_P-001" (hatched Horizontal grid 0.2 track 0.2, pour order 387): 120.208,106.271 120.203,106.276 119.085,106.276 118.74,105.931 118.74,104.596 118.956,104.38 120.185,104.38 120.282,104.477 120.282,106.202 120.212,106.271
vcc1 on Bottom Layer "NONET_L-01_P-001" (hatched Horizontal grid 0.2 track 0.2, pour order 392): 134.566,96.393 133.597,96.393 133.215,96.011 133.215,92.237 133.418,92.034 134.802,92.034 134.935,92.168 134.935,96.024
NetR39_2 on Bottom Layer "NONET_L-01_P-001" (hatched Horizontal grid 0.2 track 0.2, pour order 393): 141.032,95.081 139.166,95.081 137.939,96.308 137.061,96.308 136.573,95.821 136.573,91.281 136.758,91.095 138.307,91.095 138.37,91.158 138.37,93.079 139.131,93.84 141.012,93.84 141.115,93.942 141.115,94.998
D24A on Bottom Layer "NONET_L-01_P-001" (hatched Horizontal grid 0.2 track 0.2, pour order 394): 133.336,90.641 133.336,87.933 133.59,87.678 135.159,87.678 135.484,88.004 136.999,88.004 137.062,88.068 137.062,88.8 135.1,90.762 133.457,90.762
C48-1 on Bottom Layer "NONET_L-01_P-001" (hatched Horizontal grid 0.2 track 0.2, pour order 395): 133.512,85.806 133.506,85.812 133.506,86.509 133.705,86.708 136.312,86.708 136.406,86.801 137.716,86.801 137.812,86.706 137.812,85.739 137.76,85.687 133.637,85.687 133.515,85.808
Q21-C on Bottom Layer "NONET_L-01_P-001" (hatched Horizontal grid 0.2 track 0.2, pour order 396): 142.523,88.773 140.599,88.773 140.254,89.118 139.095,89.118 138.661,88.683 138.661,85.237 138.282,84.858 138.282,84.329 139.271,83.339 141.473,83.339 142.704,84.57 142.704,88.593
r13 on Bottom Layer "NONET_L-01_P-001" (hatched Horizontal grid 0.2 track 0.2, pour order 398): 143.806,93.48 143.795,93.491 142.709,93.491 141.953,92.734 139.781,92.734 139.493,92.447 139.493,91.191 139.695,90.988 141.697,90.988 142.677,90.009 143.836,90.009 143.997,90.169 143.997,93.299 143.816,93.48
r75 on Bottom Layer "NONET_L-01_P-001" (hatched Horizontal grid 0.2 track 0.2, pour order 399): 146.831,93.635 145.077,93.635 144.771,93.329 144.771,90.208 144.906,90.073 146.112,90.073 147.038,90.999 147.038,93.438 146.838,93.639
d22 on Bottom Layer "NONET_L-01_P-001" (hatched Horizontal grid 0.2 track 0.2, pour order 400): 20 vertices, not listed, extent 142.987,94.859 146.955,101.913
q18b on Bottom Layer "NONET_L-01_P-001" (hatched Horizontal grid 0.2 track 0.2, pour order 401): 145.572,104.094 143.384,104.094 142.13,105.348 140.833,105.348 140.674,105.19 140.674,104.202 140.881,103.994 141.671,103.994 142.725,102.94 145.508,102.94 145.727,103.159 145.727,103.939 145.565,104.101
GND on Bottom Layer "NONET_L-01_P-001" (hatched Horizontal grid 0.2 track 0.2, pour order 402): 138.385,104.485 138.382,104.482 136.836,104.482 136.612,104.258 136.612,103.587 136.773,103.426 138.336,103.426 138.532,103.621 138.532,104.333 138.379,104.485
VCC_EXT on Bottom Layer "NONET_L-01_P-001" (hatched Horizontal grid 0.2 track 0.2, pour order 403): 147.34,106.537 146.237,106.537 145.858,106.158 145.858,105.139 146.616,104.381 146.616,103.334 146.883,103.067 147.769,103.067 147.925,103.223 147.925,105.952
VCC_EXT on Bottom Layer "NONET_L-01_P-001" (hatched Horizontal grid 0.2 track 0.2, pour order 404): 137.745,83.314 137.288,82.857 135.572,82.857 135.35,82.634 135.35,81.774 135.482,81.641 138.076,81.641 138.269,81.834 138.269,83.086 138.034,83.321 137.739,83.321
NetFR3_1 on Bottom Layer "NONET_L-01_P-001" (hatched Horizontal grid 0.2 track 0.2, pour order 405): 147.709,85.615 146.71,85.615 146.236,85.141 146.236,79.717 146.55,79.403 147.571,79.403 147.973,79.805 147.973,85.359 147.717,85.614
NetC22_2 on Bottom Layer "NONET_L-01_P-001" (hatched Horizontal grid 0.2 track 0.2, pour order 406): 147.522,88.388 146.086,88.388 145.937,88.239 145.937,86.558 146.083,86.413 147.676,86.413 147.844,86.581 147.844,88.066
PGND on Bottom Layer "NONET_L-01_P-001" (hatched Horizontal grid 0.2 track 0.2, pour order 407): 145.158,88.758 143.942,88.758 143.708,88.524 143.708,84.407 142.487,83.185 142.487,81.776 142.487,79.641 142.593,79.535 145.207,79.535 145.349,79.677 145.349,82.922 145.349,88.566
PGND on Bottom Layer "NONET_L-01_P-001" (hatched Horizontal grid 0.2 track 0.2, pour order 408): 136.574,84.791 134.034,84.791 133.995,84.752 133.995,84.115 134.439,83.671 136.675,83.671 136.812,83.808 136.812,84.553
VCC_EXT on Bottom Layer "NONET_L-01_P-001" (hatched Horizontal grid 0.2 track 0.2, pour order 410): 147.558,109.363 147.553,109.367 146.244,109.367 146.017,109.14 146.017,106.316 145.858,106.158 146.065,105.952 147.925,105.952 147.925,108.997 147.561,109.361
NetD12_A on Bottom Layer "NONET_L-01_P-001" (hatched Horizontal grid 0.2 track 0.2, pour order 411): 145.203,109.357 145.196,109.365 143.507,109.365 143.278,109.135 143.278,108.196 143.554,107.919 145.16,107.919 145.345,108.105 145.345,109.219 145.207,109.357
VCC_EXT on Bottom Layer "NONET_L-01_P-001" (hatched Horizontal grid 0.2 track 0.2, pour order 412): 130.068,86.264 131.672,86.264 132.04,85.896 132.04,83.771 132.843,82.969 137.72,82.969 138.037,82.652 138.037,81.765 137.907,81.635 133.755,81.635 132.04,83.35 129.933,85.457 129.933,86.129
PGND on Bottom Layer "NONET_L-01_P-001" (hatched Horizontal grid 0.2 track 0.2, pour order 414): 133.051,84.791 132.842,84.582 132.842,83.693 132.957,83.578 136.582,83.578 136.812,83.808 136.812,84.553 136.574,84.791
NetC15_2 on Bottom Layer "NONET_L-01_P-001" (hatched Horizontal grid 0.2 track 0.2, pour order 416): 128.127,86.258 126.883,86.258 125.381,84.756 123.958,84.756 123.689,84.487 123.689,83.357 124.172,82.874 128.161,82.874 128.349,83.062 128.349,86.036
NetC15_2 on Bottom Layer "NONET_L-01_P-001" (hatched Horizontal grid 0.2 track 0.2, pour order 420): 123.698,84.415 123.698,86.291 123.698,87.127 123.945,87.374 125.101,87.374 126.217,86.258 128.181,86.258 126.338,84.415
NetC12_2 on Bottom Layer "NONET_L-01_P-001" (hatched Horizontal grid 0.2 track 0.2, pour order 424): 114.552,88.899 114.552,85.473 115.049,84.976 118.408,84.976 118.523,85.09 118.523,86.336 118.403,86.456 115.905,86.456 115.26,87.101 115.26,88.279 114.607,88.932
Q21-B on Bottom Layer "NONET_L-01_P-001" (hatched Horizontal grid 0.2 track 0.2, pour order 425): 141.407,82.673 141.403,82.677 139.523,82.677 138.878,82.032 138.878,79.838 138.867,79.827 138.926,79.768 141.357,79.768 141.591,80.001 141.591,82.488 141.404,82.675
NetR28_1 on Bottom Layer "NONET_L-01_P-001" (hatched Horizontal grid 0.2 track 0.2, pour order 426): 129.246,82.993 129.251,82.998 129.251,84.064 129.365,84.179 130.533,84.179 131.075,83.636 131.075,83.099 130.864,82.887 129.347,82.887 129.237,82.998
NetD10_2 on Bottom Layer "NONET_L-01_P-001" (hatched Horizontal grid 0.2 track 0.2, pour order 428): 136.093,81.065 136.088,81.07 134.803,81.07 134.737,81.003 134.737,79.683 134.773,79.647 136.078,79.647 136.193,79.763 136.193,80.96 136.084,81.069
NetR28_1 on Bottom Layer "NONET_L-01_P-001" (hatched Horizontal grid 0.2 track 0.2, pour order 429): 138.049,81.026 136.673,81.026 136.557,80.91 136.557,79.689 136.627,79.618 137.992,79.618 138.139,79.765 138.139,80.936 138.051,81.024
GND on Bottom Layer "NONET_L-01_P-001" (hatched Horizontal grid 0.2 track 0.2, pour order 430): 17 vertices, not listed, extent 114.968,86.973 125.353,98.83
NetC12_2 on Bottom Layer "NONET_L-01_P-001" (hatched Horizontal grid 0.2 track 0.2, pour order 431): 112.776,98.425 112.776,94.933 114.494,93.215 114.522,93.215 114.554,93.247 114.554,97.307
300V on Bottom Layer "NONET_L-01_P-001" (hatched Horizontal grid 0.2 track 0.2, pour order 432): 97.719,75.875 97.719,73.731 99.92,71.501 99.92,69.961 96.476,66.517 92.249,66.517 91.875,66.891 91.875,72.881 96.294,77.3
GND on Bottom Layer "NONET_L-01_P-001" (hatched Horizontal grid 0.2 track 0.2, pour order 435): 28 vertices, not listed, extent 60.601,53.002 108.376,89.358
NetBD1_1 on Bottom Layer "NONET_L-01_P-001" (hatched Horizontal grid 0.2 track 0.2, pour order 438): 94.085,54.746 94.085,56.92 94.736,57.571 96.978,57.571 97.61,56.938 97.61,54.799 97.359,54.547 94.284,54.547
